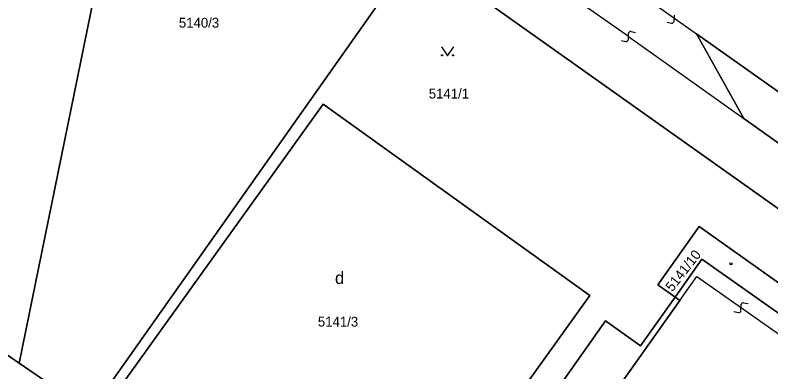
# Model space of a CAD drawing. Extents: x -400488 to -400124, y -1251493 to -1251223.
# Drawn here: x -400361.06 to -400324.23, y -1251287.06 to -1251269.65 of the extents above; entities that cross this region are included whole.
import ezdxf

# ---------------------------------------------------------------- set-up
doc = ezdxf.new("R2010")
doc.units = 0
doc.layers.add('Level 63', color=7, linetype='Continuous')

msp = doc.modelspace()

# ---------------------------------------------------------------- linework, layer by layer
at = {"layer": 'Level 63'}
for p, q in [((-400360.87, -1251286.63), (-400354.85, -1251257.19)), ((-400354.85, -1251257.19), (-400360.87, -1251286.63)), ((-400357.4, -1251289), (-400341.55, -1251266.53)), ((-400341.55, -1251266.53), (-400357.4, -1251289)), ((-400341.55, -1251266.53), (-400302.68, -1251294.16)), ((-400302.68, -1251294.16), (-400341.55, -1251266.53)), ((-400331.17, -1251270.69), (-400334.48, -1251268.34)), ((-400330.02, -1251269.03), (-400327.86, -1251270.56)), ((-400328.946, -1251269.942), (-400328.934, -1251269.648)), ((-400329.285, -1251269.988), (-400329.067, -1251270.036)), ((-400331.176, -1251270.837), (-400331.164, -1251270.543)), ((-400331.17, -1251270.69), (-400325.55, -1251274.7)), ((-400331.043, -1251270.449), (-400330.825, -1251270.497)), ((-400327.86, -1251270.56), (-400310.49, -1251282.91)), ((-400325.55, -1251274.7), (-400327.86, -1251270.56)), ((-400327.86, -1251270.56), (-400325.55, -1251274.7)), ((-400310.49, -1251282.91), (-400327.86, -1251270.56)), ((-400331.515, -1251270.883), (-400331.297, -1251270.931)), ((-400340.29, -1251271.19), (-400339.99, -1251271.64)), ((-400339.99, -1251271.64), (-400339.69, -1251271.19)), ((-400357.01, -1251289.27), (-400346.05, -1251274)), ((-400346.05, -1251274), (-400357.01, -1251289.27)), ((-400346.05, -1251274), (-400333.05, -1251283.33)), ((-400333.05, -1251283.33), (-400346.05, -1251274)), ((-400311.69, -1251284.59), (-400325.55, -1251274.7)), ((-400325.55, -1251274.7), (-400311.69, -1251284.59)), ((-400327.73, -1251279.97), (-400329.74, -1251282.81)), ((-400329.74, -1251282.81), (-400327.73, -1251279.97)), ((-400322.61, -1251283.6), (-400327.73, -1251279.97)), ((-400327.73, -1251279.97), (-400322.61, -1251283.6)), ((-400327.59, -1251281.56), (-400328.9, -1251283.41)), ((-400328.9, -1251283.41), (-400327.59, -1251281.56)), ((-400323.31, -1251284.59), (-400327.59, -1251281.56)), ((-400327.59, -1251281.56), (-400323.31, -1251284.59)), ((-400367.27, -1251282.25), (-400360.87, -1251286.63)), ((-400360.87, -1251286.63), (-400367.27, -1251282.25)), ((-400328.67, -1251283.57), (-400327.84, -1251282.41)), ((-400327.84, -1251282.41), (-400323.53, -1251285.44)), ((-400329.74, -1251282.81), (-400328.9, -1251283.41)), ((-400328.9, -1251283.41), (-400329.74, -1251282.81)), ((-400333.05, -1251283.33), (-400342.41, -1251296.38)), ((-400342.41, -1251296.38), (-400333.05, -1251283.33)), ((-400328.67, -1251283.57), (-400335.97, -1251293.9)), ((-400335.97, -1251293.9), (-400328.67, -1251283.57)), ((-400328.9, -1251283.41), (-400330.58, -1251285.79)), ((-400330.58, -1251285.79), (-400328.9, -1251283.41)), ((-400328.9, -1251283.41), (-400328.67, -1251283.57)), ((-400328.67, -1251283.57), (-400328.9, -1251283.41)), ((-400325.691, -1251284.072), (-400325.679, -1251283.778)), ((-400325.558, -1251283.684), (-400325.34, -1251283.732)), ((-400326.03, -1251284.118), (-400325.812, -1251284.166)), ((-400332.29, -1251284.57), (-400337.2, -1251291.5)), ((-400337.2, -1251291.5), (-400332.29, -1251284.57)), ((-400330.58, -1251285.79), (-400332.29, -1251284.57)), ((-400332.29, -1251284.57), (-400330.58, -1251285.79)), ((-400357.4, -1251289), (-400360.87, -1251286.63)), ((-400360.87, -1251286.63), (-400357.4, -1251289))]:
    msp.add_line(p, q, dxfattribs=at)
for centre, radius in [((-400340.26, -1251271.61), 0.03), ((-400339.72, -1251271.61), 0.03), ((-400326.17, -1251281.786), 0.054)]:
    msp.add_circle(centre, radius, dxfattribs=at)
for centre, start, end in [((-400329.046, -1251269.938), 257.753, 357.7631), ((-400331.064, -1251270.547), 77.7527, 177.7631), ((-400331.276, -1251270.833), 257.753, 357.7631), ((-400325.579, -1251283.782), 77.7527, 177.7631), ((-400325.791, -1251284.068), 257.753, 357.7631)]:
    msp.add_arc(centre, 0.1, start, end, dxfattribs=at)

# ---------------------------------------------------------------- texts
for s, height, p in [('5140/3', 0.48, (-400353.083, -1251270.26)), ('5141/1', 0.48, (-400340.904, -1251273.72)), ('d', 0.6, (-400345.473, -1251282.77)), ('5141/3', 0.48, (-400346.308, -1251284.85))]:
    msp.add_text(s, height=height, dxfattribs=at).set_placement(p)
msp.add_text('5141/10', height=0.48, rotation=52.0061, dxfattribs=at).set_placement((-400329.032, -1251283.178))

doc.saveas('drawing.dxf')
